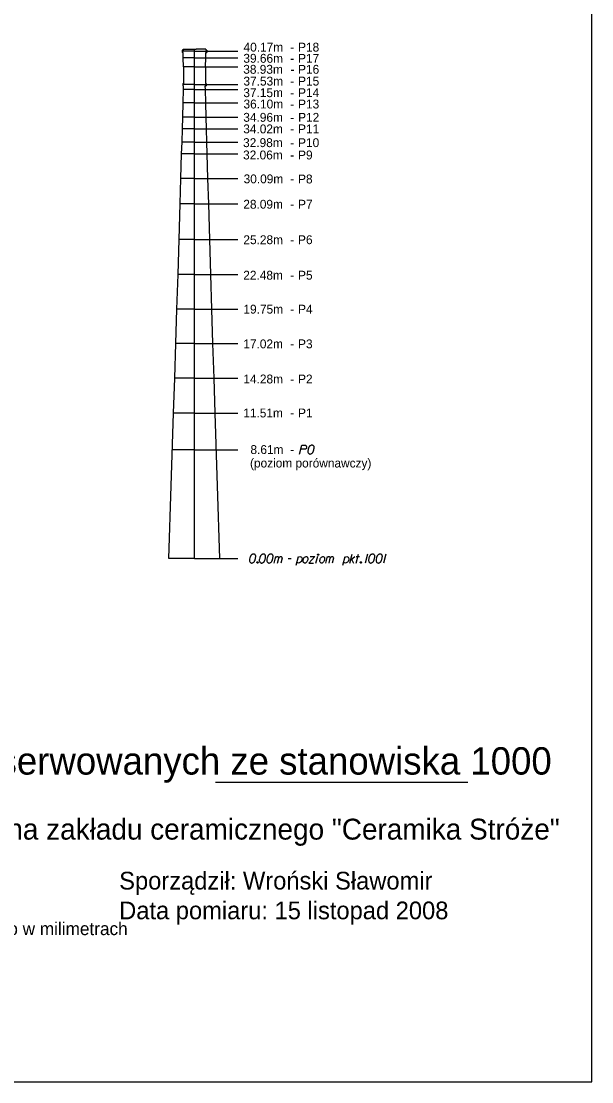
# Model space of a CAD drawing. Extents: x 138 to 264, y -75 to 121.
# Drawn here: x 180.2 to 190.1, y 2.29 to 20.71 of the extents above; entities that cross this region are included whole.
import ezdxf

# ---------------------------------------------------------------- set-up
doc = ezdxf.new("R2010")
doc.units = 0
doc.layers.add('Opisy', color=7, linetype='Continuous')
doc.layers.add('Ramka do drukowania', color=7, linetype='Continuous')

msp = doc.modelspace()

# ---------------------------------------------------------------- linework, layer by layer
at = {"layer": 'Opisy'}
for p, q in [((182.991, 20.204), (182.991, 20.185)), ((183.008, 20.204), (182.991, 20.204)), ((183.204, 20.185), (182.991, 20.185)), ((182.991, 20.185), (182.991, 20.166)), ((183.008, 20.166), (182.991, 20.166)), ((183.008, 20.222), (183.008, 20.204)), ((183.008, 20.222), (183.234, 20.222)), ((183.008, 20.072), (183.008, 20.166)), ((183.204, 11.376), (183.204, 20.222)), ((183.204, 20.185), (183.957, 20.185)), ((183.4, 20.222), (183.234, 20.222)), ((183.4, 20.222), (183.4, 20.204)), ((183.4, 20.204), (183.417, 20.204)), ((183.4, 20.166), (183.417, 20.166)), ((183.4, 20.072), (183.4, 20.166)), ((183.417, 20.204), (183.417, 20.185)), ((183.417, 20.185), (183.417, 20.166)), ((183.204, 20.072), (183.008, 20.072)), ((183.014, 19.912), (183.008, 20.072)), ((183.204, 19.912), (183.014, 19.912)), ((183.014, 19.912), (183.014, 19.624)), ((183.204, 20.072), (183.957, 20.072)), ((183.204, 19.912), (183.957, 19.912)), ((183.394, 19.912), (183.4, 20.072)), ((183.394, 19.912), (183.394, 19.624)), ((183.001, 19.624), (183.001, 19.605)), ((183.001, 19.624), (183.014, 19.624)), ((183.204, 19.605), (183.001, 19.605)), ((183.001, 19.605), (183.001, 19.586)), ((183.016, 19.586), (183.001, 19.586)), ((183.014, 19.522), (183.016, 19.586)), ((183.204, 19.605), (183.957, 19.605)), ((183.394, 19.522), (183.392, 19.586)), ((183.392, 19.586), (183.407, 19.586)), ((183.407, 19.624), (183.394, 19.624)), ((183.407, 19.624), (183.407, 19.605)), ((183.407, 19.605), (183.407, 19.586)), ((183.008, 19.291), (183.014, 19.522)), ((183.204, 19.522), (183.014, 19.522)), ((183.204, 19.522), (183.957, 19.522)), ((183.4, 19.291), (183.394, 19.522)), ((183.001, 19.041), (183.008, 19.291)), ((183.204, 19.291), (183.008, 19.291)), ((183.204, 19.291), (183.957, 19.291)), ((183.407, 19.041), (183.4, 19.291)), ((182.994, 18.835), (183.001, 19.041)), ((183.204, 19.041), (183.001, 19.041)), ((183.204, 19.041), (183.957, 19.041)), ((183.413, 18.835), (183.407, 19.041)), ((182.989, 18.607), (182.994, 18.835)), ((183.204, 18.835), (182.994, 18.835)), ((183.204, 18.835), (183.957, 18.835)), ((183.419, 18.607), (183.413, 18.835)), ((182.981, 18.405), (182.989, 18.607)), ((183.204, 18.607), (182.989, 18.607)), ((183.204, 18.607), (183.957, 18.607)), ((183.426, 18.405), (183.419, 18.607)), ((182.969, 17.973), (182.981, 18.405)), ((183.204, 18.405), (182.981, 18.405)), ((183.204, 18.405), (183.957, 18.405)), ((183.438, 17.973), (183.426, 18.405)), ((182.956, 17.535), (182.969, 17.973)), ((183.204, 17.973), (182.969, 17.973)), ((183.204, 17.973), (183.957, 17.973)), ((183.452, 17.535), (183.438, 17.973)), ((182.939, 16.918), (182.956, 17.535)), ((183.204, 17.535), (182.956, 17.535)), ((183.204, 17.535), (183.957, 17.535)), ((183.469, 16.918), (183.452, 17.535)), ((182.919, 16.305), (182.939, 16.918)), ((183.204, 16.918), (182.939, 16.918)), ((183.204, 16.918), (183.957, 16.918)), ((183.489, 16.305), (183.469, 16.918)), ((182.9, 15.706), (182.919, 16.305)), ((183.204, 16.305), (182.919, 16.305)), ((183.204, 16.305), (183.957, 16.305)), ((183.508, 15.706), (183.489, 16.305)), ((182.882, 15.108), (182.9, 15.706)), ((183.204, 15.706), (182.9, 15.706)), ((183.204, 15.706), (183.957, 15.706)), ((183.526, 15.108), (183.508, 15.706)), ((182.863, 14.506), (182.882, 15.108)), ((183.204, 15.108), (182.882, 15.108)), ((183.204, 15.108), (183.957, 15.108)), ((183.545, 14.506), (183.526, 15.108)), ((182.843, 13.9), (182.863, 14.506)), ((183.204, 14.506), (182.863, 14.506)), ((183.204, 14.506), (183.957, 14.506)), ((183.565, 13.9), (183.545, 14.506)), ((182.761, 11.376), (182.843, 13.9)), ((183.204, 13.9), (182.843, 13.9)), ((183.204, 13.9), (183.957, 13.9)), ((183.647, 11.376), (183.565, 13.9)), ((183.204, 13.263), (182.822, 13.263)), ((183.204, 13.263), (183.957, 13.263)), ((183.204, 11.376), (182.761, 11.376)), ((183.204, 11.376), (183.957, 11.376)), ((183.569, 7.488), (187.953, 7.488))]:
    msp.add_line(p, q, dxfattribs=at)
for points in [[(185.026, 13.189), (185.067, 13.343), (185.12, 13.343), (185.127, 13.342), (185.13, 13.34), (185.138, 13.337), (185.143, 13.333), (185.146, 13.328), (185.15, 13.322), (185.152, 13.314), (185.154, 13.306), (185.152, 13.3), (185.151, 13.295), (185.149, 13.291), (185.146, 13.287), (185.143, 13.282), (185.138, 13.278), (185.134, 13.276), (185.128, 13.274), (185.122, 13.272), (185.049, 13.272)], [(185.247, 13.343), (185.245, 13.343), (185.237, 13.342), (185.232, 13.34), (185.229, 13.339), (185.223, 13.337), (185.215, 13.333), (185.209, 13.329), (185.203, 13.325), (185.2, 13.32), (185.196, 13.314), (185.192, 13.308), (185.189, 13.3), (185.186, 13.295), (185.184, 13.288), (185.18, 13.276), (185.177, 13.258), (185.174, 13.243), (185.174, 13.23), (185.175, 13.22), (185.18, 13.209), (185.184, 13.203), (185.19, 13.196), (185.197, 13.191), (185.201, 13.19), (185.208, 13.189), (185.214, 13.189), (185.224, 13.19), (185.232, 13.192), (185.239, 13.196), (185.247, 13.202), (185.251, 13.206), (185.256, 13.21), (185.259, 13.215), (185.262, 13.219), (185.264, 13.225), (185.265, 13.227), (185.268, 13.234), (185.27, 13.241), (185.272, 13.248), (185.274, 13.253), (185.275, 13.257), (185.276, 13.261), (185.279, 13.272), (185.28, 13.278), (185.281, 13.285), (185.282, 13.293), (185.283, 13.304), (185.283, 13.308), (185.282, 13.312), (185.281, 13.317), (185.277, 13.325), (185.274, 13.329), (185.27, 13.333), (185.265, 13.337), (185.26, 13.339), (185.257, 13.34), (185.253, 13.342), (185.247, 13.343)], [(184.233, 11.45), (184.231, 11.45), (184.223, 11.449), (184.219, 11.448), (184.215, 11.447), (184.209, 11.444), (184.202, 11.441), (184.196, 11.437), (184.189, 11.432), (184.186, 11.427), (184.182, 11.421), (184.179, 11.415), (184.175, 11.408), (184.172, 11.403), (184.17, 11.396), (184.166, 11.384), (184.163, 11.365), (184.16, 11.351), (184.16, 11.337), (184.162, 11.328), (184.166, 11.317), (184.17, 11.311), (184.176, 11.303), (184.183, 11.299), (184.187, 11.297), (184.194, 11.296), (184.2, 11.296), (184.21, 11.297), (184.219, 11.3), (184.225, 11.303), (184.233, 11.31), (184.237, 11.313), (184.242, 11.318), (184.245, 11.323), (184.248, 11.327), (184.25, 11.333), (184.251, 11.335), (184.254, 11.341), (184.256, 11.348), (184.259, 11.356), (184.26, 11.361), (184.261, 11.364), (184.262, 11.369), (184.265, 11.38), (184.266, 11.386), (184.267, 11.392), (184.268, 11.401), (184.27, 11.412), (184.27, 11.415), (184.268, 11.42), (184.267, 11.425), (184.263, 11.432), (184.26, 11.437), (184.256, 11.441), (184.251, 11.444), (184.246, 11.447), (184.243, 11.448), (184.239, 11.449), (184.233, 11.45)], [(184.404, 11.45), (184.402, 11.45), (184.395, 11.449), (184.39, 11.448), (184.386, 11.447), (184.38, 11.444), (184.373, 11.441), (184.367, 11.437), (184.361, 11.432), (184.357, 11.427), (184.353, 11.421), (184.35, 11.415), (184.346, 11.408), (184.344, 11.403), (184.341, 11.396), (184.338, 11.384), (184.334, 11.365), (184.331, 11.351), (184.331, 11.337), (184.333, 11.328), (184.338, 11.317), (184.341, 11.311), (184.347, 11.303), (184.355, 11.299), (184.358, 11.297), (184.365, 11.296), (184.372, 11.296), (184.381, 11.297), (184.39, 11.3), (184.396, 11.303), (184.404, 11.31), (184.408, 11.313), (184.413, 11.318), (184.416, 11.323), (184.419, 11.327), (184.421, 11.333), (184.422, 11.335), (184.425, 11.341), (184.427, 11.348), (184.43, 11.356), (184.431, 11.361), (184.432, 11.364), (184.433, 11.369), (184.436, 11.38), (184.437, 11.386), (184.438, 11.392), (184.439, 11.401), (184.441, 11.412), (184.441, 11.415), (184.439, 11.42), (184.438, 11.425), (184.435, 11.432), (184.431, 11.437), (184.427, 11.441), (184.422, 11.444), (184.418, 11.447), (184.414, 11.448), (184.41, 11.449), (184.404, 11.45)], [(184.534, 11.45), (184.532, 11.45), (184.524, 11.449), (184.52, 11.448), (184.516, 11.447), (184.51, 11.444), (184.503, 11.441), (184.497, 11.437), (184.49, 11.432), (184.487, 11.427), (184.483, 11.421), (184.48, 11.415), (184.476, 11.408), (184.473, 11.403), (184.471, 11.396), (184.467, 11.384), (184.464, 11.365), (184.461, 11.351), (184.461, 11.337), (184.463, 11.328), (184.467, 11.317), (184.471, 11.311), (184.477, 11.303), (184.484, 11.299), (184.488, 11.297), (184.495, 11.296), (184.501, 11.296), (184.511, 11.297), (184.52, 11.3), (184.526, 11.303), (184.534, 11.31), (184.538, 11.313), (184.543, 11.318), (184.546, 11.323), (184.549, 11.327), (184.551, 11.333), (184.552, 11.335), (184.555, 11.341), (184.557, 11.348), (184.56, 11.356), (184.561, 11.361), (184.562, 11.364), (184.563, 11.369), (184.566, 11.38), (184.567, 11.386), (184.568, 11.392), (184.569, 11.401), (184.571, 11.412), (184.571, 11.415), (184.569, 11.42), (184.568, 11.425), (184.565, 11.432), (184.561, 11.437), (184.557, 11.441), (184.552, 11.444), (184.548, 11.447), (184.544, 11.448), (184.54, 11.449), (184.534, 11.45)], [(185.349, 11.45), (185.355, 11.45), (185.358, 11.448), (185.362, 11.443), (185.362, 11.437), (185.358, 11.432), (185.355, 11.43), (185.349, 11.43), (185.345, 11.432), (185.341, 11.437), (185.341, 11.443), (185.345, 11.448), (185.349, 11.45)], [(185.905, 11.296), (185.946, 11.45)], [(186.013, 11.296), (186.053, 11.45)], [(186.208, 11.45), (186.167, 11.296)], [(186.302, 11.45), (186.299, 11.45), (186.292, 11.449), (186.287, 11.448), (186.283, 11.447), (186.277, 11.444), (186.27, 11.441), (186.264, 11.437), (186.258, 11.432), (186.254, 11.427), (186.251, 11.421), (186.247, 11.415), (186.243, 11.408), (186.241, 11.403), (186.238, 11.396), (186.235, 11.384), (186.231, 11.365), (186.229, 11.351), (186.229, 11.337), (186.23, 11.328), (186.235, 11.317), (186.238, 11.311), (186.245, 11.303), (186.252, 11.299), (186.255, 11.297), (186.263, 11.296), (186.269, 11.296), (186.279, 11.297), (186.287, 11.3), (186.293, 11.303), (186.302, 11.31), (186.305, 11.313), (186.31, 11.318), (186.314, 11.323), (186.316, 11.327), (186.319, 11.333), (186.32, 11.335), (186.322, 11.341), (186.325, 11.348), (186.327, 11.356), (186.328, 11.361), (186.33, 11.364), (186.331, 11.369), (186.333, 11.38), (186.334, 11.386), (186.336, 11.392), (186.337, 11.401), (186.338, 11.412), (186.338, 11.415), (186.337, 11.42), (186.336, 11.425), (186.332, 11.432), (186.328, 11.437), (186.325, 11.441), (186.32, 11.444), (186.315, 11.447), (186.311, 11.448), (186.308, 11.449), (186.302, 11.45)], [(186.431, 11.45), (186.429, 11.45), (186.422, 11.449), (186.417, 11.448), (186.413, 11.447), (186.407, 11.444), (186.4, 11.441), (186.394, 11.437), (186.388, 11.432), (186.384, 11.427), (186.38, 11.421), (186.377, 11.415), (186.373, 11.408), (186.371, 11.403), (186.368, 11.396), (186.365, 11.384), (186.361, 11.365), (186.359, 11.351), (186.359, 11.337), (186.36, 11.328), (186.365, 11.317), (186.368, 11.311), (186.374, 11.303), (186.382, 11.299), (186.385, 11.297), (186.393, 11.296), (186.399, 11.296), (186.408, 11.297), (186.417, 11.3), (186.423, 11.303), (186.431, 11.31), (186.435, 11.313), (186.44, 11.318), (186.444, 11.323), (186.446, 11.327), (186.448, 11.333), (186.45, 11.335), (186.452, 11.341), (186.455, 11.348), (186.457, 11.356), (186.458, 11.361), (186.459, 11.364), (186.461, 11.369), (186.463, 11.38), (186.464, 11.386), (186.465, 11.392), (186.467, 11.401), (186.468, 11.412), (186.468, 11.415), (186.467, 11.42), (186.465, 11.425), (186.462, 11.432), (186.458, 11.437), (186.455, 11.441), (186.45, 11.444), (186.445, 11.447), (186.441, 11.448), (186.438, 11.449), (186.431, 11.45)], [(186.53, 11.45), (186.489, 11.296)], [(184.297, 11.317), (184.304, 11.317), (184.307, 11.314), (184.311, 11.31), (184.311, 11.303), (184.307, 11.299), (184.304, 11.296), (184.297, 11.296), (184.294, 11.299), (184.29, 11.303), (184.29, 11.31), (184.294, 11.314), (184.297, 11.317)], [(184.591, 11.296), (184.619, 11.407)], [(184.612, 11.378), (184.618, 11.391), (184.624, 11.398), (184.631, 11.403), (184.639, 11.407), (184.643, 11.409), (184.651, 11.409), (184.653, 11.408), (184.658, 11.403), (184.663, 11.397), (184.666, 11.386), (184.668, 11.38), (184.674, 11.391), (184.681, 11.398), (184.688, 11.403), (184.696, 11.407), (184.702, 11.409), (184.708, 11.409), (184.713, 11.408), (184.716, 11.403), (184.72, 11.397), (184.724, 11.386), (184.725, 11.38), (184.704, 11.296)], [(184.647, 11.296), (184.668, 11.38)], [(184.834, 11.374), (184.886, 11.374)], [(184.969, 11.256), (185.01, 11.408)], [(185.006, 11.395), (185.019, 11.404), (185.037, 11.408), (185.051, 11.405), (185.061, 11.398), (185.068, 11.388), (185.073, 11.375), (185.074, 11.363), (185.072, 11.352), (185.068, 11.339), (185.059, 11.324), (185.047, 11.311), (185.028, 11.299), (185.013, 11.296), (184.998, 11.297), (184.982, 11.306)], [(185.142, 11.408), (185.151, 11.408), (185.161, 11.403), (185.17, 11.39), (185.172, 11.384), (185.173, 11.378), (185.173, 11.373), (185.173, 11.354), (185.169, 11.342), (185.163, 11.328), (185.156, 11.316), (185.144, 11.305), (185.133, 11.296), (185.115, 11.296), (185.107, 11.299), (185.1, 11.305), (185.096, 11.311), (185.091, 11.325), (185.091, 11.347), (185.094, 11.354), (185.099, 11.37), (185.104, 11.379), (185.106, 11.384), (185.118, 11.397), (185.13, 11.404), (185.142, 11.408)], [(185.215, 11.41), (185.294, 11.41), (185.193, 11.296), (185.271, 11.296)], [(185.315, 11.296), (185.346, 11.414)], [(185.434, 11.408), (185.442, 11.408), (185.452, 11.403), (185.462, 11.39), (185.463, 11.384), (185.464, 11.378), (185.464, 11.373), (185.464, 11.354), (185.46, 11.342), (185.454, 11.328), (185.447, 11.316), (185.435, 11.305), (185.424, 11.296), (185.406, 11.296), (185.399, 11.299), (185.391, 11.305), (185.388, 11.311), (185.383, 11.325), (185.383, 11.347), (185.385, 11.354), (185.39, 11.37), (185.395, 11.379), (185.397, 11.384), (185.409, 11.397), (185.422, 11.404), (185.434, 11.408)], [(185.485, 11.296), (185.513, 11.407)], [(185.505, 11.378), (185.511, 11.391), (185.517, 11.398), (185.525, 11.403), (185.532, 11.407), (185.537, 11.409), (185.544, 11.409), (185.547, 11.408), (185.551, 11.403), (185.556, 11.397), (185.56, 11.386), (185.561, 11.38), (185.567, 11.391), (185.575, 11.398), (185.582, 11.403), (185.589, 11.407), (185.595, 11.409), (185.601, 11.409), (185.606, 11.408), (185.61, 11.403), (185.613, 11.397), (185.617, 11.386), (185.618, 11.38), (185.598, 11.296)], [(185.541, 11.296), (185.561, 11.38)], [(185.782, 11.256), (185.823, 11.408)], [(185.82, 11.395), (185.832, 11.404), (185.85, 11.408), (185.865, 11.405), (185.874, 11.398), (185.882, 11.388), (185.887, 11.375), (185.888, 11.363), (185.885, 11.352), (185.882, 11.339), (185.872, 11.324), (185.86, 11.311), (185.842, 11.299), (185.826, 11.296), (185.811, 11.297), (185.795, 11.306)], [(185.919, 11.351), (185.992, 11.412)], [(185.934, 11.363), (185.965, 11.296)], [(186.013, 11.408), (186.071, 11.408)], [(186.092, 11.317), (186.098, 11.317), (186.101, 11.314), (186.105, 11.31), (186.105, 11.303), (186.101, 11.299), (186.098, 11.296), (186.092, 11.296), (186.088, 11.299), (186.084, 11.303), (186.084, 11.31), (186.088, 11.314), (186.092, 11.317)]]:
    msp.add_lwpolyline(points, dxfattribs=at)
at = {"layer": 'Ramka do drukowania'}
for p, q in [((190.105, 2.285), (190.105, 31.985)), ((169.105, 2.285), (190.105, 2.285))]:
    msp.add_line(p, q, dxfattribs=at)

# ---------------------------------------------------------------- texts
at = {"layer": 'Opisy'}
for s, height, p in [('40.17m', 0.1542, (184.057, 20.179)), ('P18', 0.1542, (185.004, 20.179)), ('39.66m', 0.1542, (184.054, 19.985)), ('-', 0.154, (184.867, 20.179)), ('P17', 0.1542, (185.004, 19.985)), ('38.93m', 0.1542, (184.052, 19.794)), ('-', 0.154, (184.868, 19.985)), ('P16', 0.1542, (185.004, 19.794)), ('37.53m', 0.1542, (184.055, 19.589)), ('-', 0.154, (184.871, 19.794)), ('P15', 0.1542, (185.004, 19.589)), ('37.15m', 0.1542, (184.053, 19.388)), ('-', 0.154, (184.867, 19.589)), ('P14', 0.1542, (185.004, 19.388)), ('36.10m', 0.1542, (184.056, 19.191)), ('-', 0.154, (184.867, 19.388)), ('P13', 0.1542, (185.004, 19.191)), ('-', 0.154, (184.868, 19.191)), ('34.96m', 0.1542, (184.053, 18.96)), ('-', 0.154, (184.868, 18.96)), ('P12', 0.1542, (185.005, 18.96)), ('34.02m', 0.1542, (184.052, 18.759)), ('-', 0.154, (184.868, 18.759)), ('P11', 0.1542, (185.004, 18.759)), ('32.98m', 0.1542, (184.049, 18.52)), ('P10', 0.1542, (185.004, 18.52)), ('32.06m', 0.1542, (184.049, 18.306)), ('-', 0.154, (184.868, 18.52)), ('P9', 0.1542, (185.004, 18.306)), ('-', 0.154, (184.868, 18.306)), ('30.09m', 0.1542, (184.058, 17.891)), ('-', 0.154, (184.868, 17.891)), ('P8', 0.1542, (185.004, 17.889)), ('28.09m', 0.1542, (184.053, 17.45)), ('-', 0.154, (184.868, 17.45)), ('P7', 0.1542, (185.004, 17.45)), ('25.28m', 0.1542, (184.054, 16.834)), ('P6', 0.1542, (185.003, 16.834)), ('-', 0.154, (184.867, 16.834)), ('22.48m', 0.1542, (184.052, 16.218)), ('-', 0.154, (184.867, 16.218)), ('P5', 0.1542, (185.004, 16.218)), ('19.75m', 0.1542, (184.055, 15.628)), ('-', 0.154, (184.867, 15.628)), ('P4', 0.1542, (185.004, 15.628)), ('17.02m', 0.1542, (184.053, 15.025)), ('P3', 0.1542, (185.004, 15.025)), ('-', 0.154, (184.867, 15.025)), ('14.28m', 0.1542, (184.054, 14.415)), ('P2', 0.1542, (185.004, 14.415)), ('-', 0.154, (184.868, 14.415)), ('11.51m', 0.1542, (184.052, 13.825)), ('-', 0.154, (184.867, 13.825)), ('P1', 0.1542, (185.004, 13.825)), ('8.61m', 0.1542, (184.177, 13.189)), ('(poziom porównawczy)', 0.15416, (184.169, 12.955)), ('-', 0.154, (184.867, 13.189)), ('Wykres wychyleń osi komina obserwowanych ze stanowiska 1000', 0.47516, (170.798, 7.621)), ('Badanie pionowości i prostoliniowości komina zakładu ceramicznego "Ceramika Stróże"', 0.36281, (170.678, 6.492)), ('Sporządził: Wroński Sławomir', 0.30766, (181.897, 5.625)), ('Data pomiaru: 15 listopad 2008', 0.30766, (181.897, 5.108)), ('Wartości wychyleń komina dla poszczególnych poziomów podano w milimetrach', 0.22315, (171.43, 4.833))]:
    msp.add_text(s, height=height, dxfattribs=at).set_placement(p)

doc.saveas('drawing.dxf')
